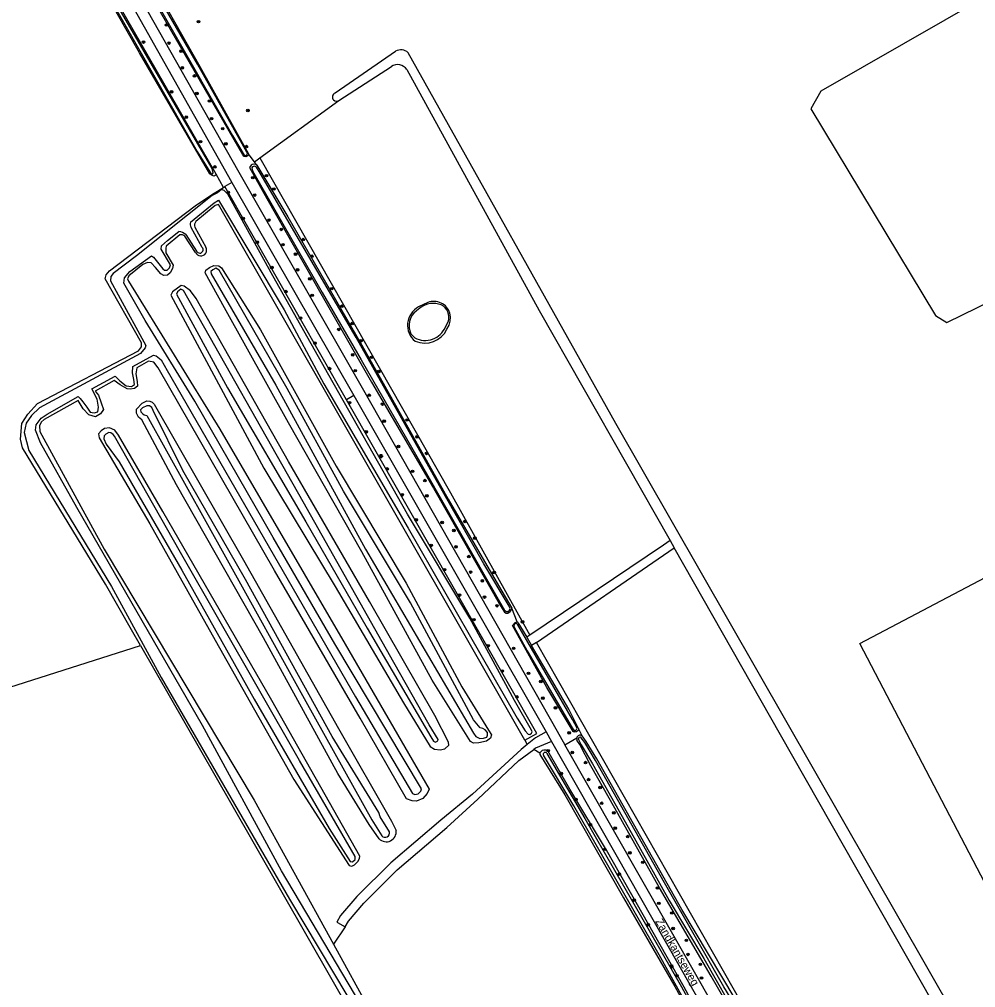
# Model space of a CAD drawing. Extents: x 140000 to 143000, y 403500 to 406000.
# Drawn here: x 140149.8 to 140448.3, y 404654.9 to 404957.2 of the extents above; entities that cross this region are included whole.
import ezdxf

# ---------------------------------------------------------------- set-up
doc = ezdxf.new("R2010")
doc.units = 0
for name, color, linetype in [('gg-anno-openbare ruimte label', 7, 'Continuous'), ('gg-knt-bronhoudergrens', 7, 'Continuous'), ('gg-knt-verharding', 7, 'Continuous'), ('gg-kntw-bovenkant insteek waterloop', 7, 'Continuous'), ('gg-kntw-waterlijn', 7, 'Continuous'), ('gt-grn-groengrens', 7, 'Continuous'), ('gt-grn-vlakafsluiter', 7, 'Continuous'), ('gt-grn-weggrens', 7, 'Continuous'), ('gt-symb-boom', 7, 'Continuous'), ('gt-symb-lichtmast', 7, 'Continuous')]:
    doc.layers.add(name, color=color, linetype=linetype)

# ---------------------------------------------------------------- blocks, each defined once
blk = doc.blocks.new('gt0-BOOM')
at = {"layer": 'gt-symb-boom'}
for radius in [0.4, 0.2]:
    blk.add_circle((0, 0), radius, dxfattribs=at)
blk = doc.blocks.new('gt0-LMAST')
at = {"layer": 'gt-symb-lichtmast'}
for p, q in [((-0.18, 0.17), (-0.45, 0.44)), ((-0.01, 0.25), (-0.01, 0.62)), ((0.17, 0.17), (0.44, 0.44)), ((-0.26, 0), (-0.63, 0)), ((-0.18, -0.18), (-0.45, -0.45)), ((-0.01, -0.25), (-0.01, -0.63)), ((0.44, -0.45), (0.17, -0.18)), ((0.24, 0), (0.62, 0))]:
    blk.add_line(p, q, dxfattribs=at)
blk.add_circle((-0.01, 0), 0.25, dxfattribs=at)

msp = doc.modelspace()

# ---------------------------------------------------------------- linework, layer by layer
at = {"layer": 'gg-knt-bronhoudergrens'}
for p, q in [((140224.82, 404913.91), (140249.53, 404931.86)), ((140311.14, 404762.64), (140354.13, 404792.19)), ((140395.71, 404614.2), (140311.14, 404762.64))]:
    msp.add_line(p, q, dxfattribs=at)
for points in [[(140224.82, 404913.91), (140284.32, 404809.37), (140309.13, 404764.88)], [(140352.87, 404794.42), (140350.82, 404793.03), (140309.13, 404764.88)]]:
    msp.add_lwpolyline(points, dxfattribs=at)
at = {"layer": 'gg-knt-verharding'}
for p, q in [((140216.06, 404906.21), (140254.21, 404839.77)), ((140254.21, 404839.77), (140314.17, 404734.67)), ((140314.17, 404734.67), (140315.85, 404731.72))]:
    msp.add_line(p, q, dxfattribs=at)
for points in [[(140015.47, 405269.29), (140093.98, 405129.51), (140149.27, 405031.32), (140217.82, 404910.2), (140257.23, 404841.36), (140317.65, 404734.89), (140320.04, 404730.7)], [(140012.59, 405267.65), (140091.15, 405127.98), (140215.94, 404906.42), (140216.06, 404906.21)], [(140315.85, 404731.72), (140371.43, 404634.06), (140428.2, 404534.96)], [(140385.43, 404616.2), (140375.32, 404633.79), (140320.04, 404730.7)]]:
    msp.add_lwpolyline(points, dxfattribs=at)
at = {"layer": 'gg-kntw-bovenkant insteek waterloop'}
for p, q in [((140267.19, 404947.17), (140248.32, 404934.15)), ((140249.53, 404931.86), (140265.87, 404942.46)), ((140213.45, 404904.71), (140213.86, 404904.97)), ((140251.83, 404838.42), (140213.86, 404904.97)), ((140204.49, 404892.26), (140208, 404886)), ((140204.73, 404884.34), (140201.41, 404889.42)), ((140277.28, 404868.8), (140274.38, 404867.36)), ((140352.87, 404794.42), (140354.13, 404792.19)), ((140308.15, 404764.22), (140309.66, 404761.63)), ((140325.38, 404733.48), (140325.47, 404733.44))]:
    msp.add_line(p, q, dxfattribs=at)
for points in [[(140211.16, 404908.87), (140180.94, 404961.44), (140141.23, 405031.76), (140139.9, 405034.84), (140106.05, 405095.67), (140094.79, 405114.98), (140091.84, 405120.15), (140090.08, 405122.65), (140083.85, 405133.69), (140065.63, 405166.05), (140041.91, 405207.98), (140024.47, 405240.13), (140013.65, 405260.82), (140011.23, 405265.23), (140010.6, 405265.67), (140009.82, 405265.58), (140008.99, 405264.87), (140008.83, 405264.18), (140008.78, 405263.08)], [(140221.32, 404915.12), (140221.27, 404914.79), (140221.05, 404914.55), (140220.48, 404914.22), (140219.96, 404914.32), (140219.52, 404914.81), (140187.96, 404969.55), (140169.57, 405002.2), (140142.8, 405050.33), (140118.75, 405092.41), (140116.73, 405096.57), (140115.86, 405097.86), (140114.98, 405099.37), (140049.1, 405216.97), (140022.7, 405263.69), (140021.65, 405265.62), (140020.77, 405267.14)], [(140022.22, 405268.24), (140023.21, 405266.5), (140053.29, 405214.48), (140091.86, 405144.38), (140113.34, 405106.43), (140117.71, 405098.64), (140120.4, 405093.58), (140120.66, 405093.21), (140144.47, 405051.89), (140170.87, 405004.52), (140206.08, 404942.46), (140221.32, 404915.12)], [(140211.16, 404908.87), (140211.14, 404908.72), (140210.91, 404908.37), (140210.58, 404908.25), (140209.72, 404908.53), (140209.26, 404908.96), (140187.27, 404946.74), (140161.57, 404991.94), (140139.8, 405030.55), (140137.59, 405034.4), (140115.65, 405072.87), (140094.35, 405111.42), (140090.14, 405119.58), (140088.48, 405122.42), (140067.9, 405158.36), (140046.49, 405195.64), (140033.29, 405218.1), (140022.54, 405238.57), (140008.78, 405263.08)], [(140442.04, 404645.58), (140335.94, 404830.98), (140271.07, 404946.74)], [(140270.7, 404941.52), (140312.04, 404866.27), (140352.87, 404794.42)], [(140223.9, 404911.62), (140223.53, 404911.88), (140222.95, 404911.95), (140222.42, 404911.84), (140222.14, 404911.63), (140221.62, 404910.94), (140226.98, 404901.2), (140244.29, 404870.8), (140259.7, 404843.87), (140278.99, 404810.74), (140299.93, 404774.07), (140301.18, 404772.08), (140301.75, 404771.81), (140302.26, 404771.76), (140302.96, 404772.32), (140303.37, 404772.76), (140303.44, 404773.3)], [(140223.9, 404911.62), (140233.54, 404895.47), (140256.69, 404855.44), (140277.3, 404818.65)], [(140187.6, 404761.63), (140184.79, 404766.54), (140176.64, 404780.8), (140150.73, 404823.38), (140150.08, 404826.13), (140150.53, 404831.02), (140152.4, 404833.86), (140155.43, 404837.23), (140186.91, 404853.66), (140187.91, 404854.92), (140187.84, 404856.18), (140176.52, 404876.1), (140176.81, 404877.43), (140177.94, 404878.64), (140204.66, 404898.91), (140210.03, 404902.56), (140213.45, 404904.71)], [(140307.53, 404732.16), (140211.89, 404899.32), (140210.91, 404899.04), (140204.82, 404894)], [(140199.83, 404889.88), (140195.55, 404886.34), (140195.47, 404885.75), (140195.43, 404884.24), (140197.78, 404880.37), (140197.6, 404879.41), (140196.85, 404878.03), (140195.98, 404877.29), (140194.85, 404877.16), (140193.93, 404877.71), (140192.2, 404879.69), (140190.89, 404881.09), (140189.77, 404881.24), (140188.29, 404880.66), (140183.94, 404877.09), (140183.51, 404876.12), (140183.78, 404875.39), (140212.37, 404829.24), (140251.41, 404762.13), (140277.65, 404716.79), (140277.08, 404715.48), (140275.75, 404713.92), (140273.68, 404713.11), (140272.36, 404713.16), (140270.61, 404713.84), (140256.18, 404739.03), (140229.39, 404785.06), (140193.13, 404848.39), (140191.71, 404850.12), (140190.07, 404850.41), (140186.41, 404848.31), (140186.16, 404846.52), (140186.49, 404844.12), (140186.61, 404842.59), (140185.71, 404841.88), (140184.33, 404841.74), (140183.4, 404841.77), (140181.23, 404843.08), (140179.37, 404844.4), (140173.38, 404841.05), (140174.41, 404839.79), (140175.29, 404837.48), (140175.98, 404835.35), (140175.1, 404834.03), (140173.56, 404833.08), (140171.48, 404833.72), (140169.63, 404835.56), (140168.09, 404838.13), (140157.48, 404832.27), (140156.59, 404831.44), (140156.04, 404830.22), (140156.13, 404828.53), (140176.26, 404791.76), (140223.05, 404713.36), (140247.77, 404668.46)], [(140233.77, 404831.23), (140213.74, 404867.14), (140207.72, 404878.05), (140207.94, 404878.8), (140209.11, 404879.73), (140210.45, 404880.33), (140212.05, 404880.2), (140212.88, 404879.61), (140225.01, 404860.25), (140248.69, 404817.66), (140270.5, 404781.1), (140287.89, 404748.74), (140296.15, 404735.25), (140297.18, 404733.81), (140296.82, 404732.72), (140295.53, 404731.84), (140293.21, 404731.27), (140291.54, 404731.21), (140290.6, 404731.73), (140278.63, 404750.88), (140256.64, 404790.88), (140233.77, 404831.23)], [(140233.73, 404819.12), (140204.92, 404870.01), (140203.14, 404872.44), (140201.21, 404873.82), (140200.22, 404874.03), (140197.55, 404872.12), (140197, 404871.03), (140226.04, 404817.06), (140248.29, 404780.09), (140269.64, 404743.79), (140278.02, 404730.13), (140279.38, 404729.34), (140281.11, 404729.09), (140282.55, 404729.36), (140283.83, 404730.6), (140283.74, 404731.53), (140279.42, 404739.85), (140259.02, 404775.38), (140233.73, 404819.12)], [(140283.23, 404860.42), (140283.87, 404861.67), (140284.23, 404862.93), (140284.35, 404864.2), (140284.17, 404865.49)], [(140262.04, 404701.34), (140258.96, 404705.82), (140249.2, 404721.72), (140225.98, 404764.05), (140198.79, 404811.82), (140187.95, 404832.12), (140186.97, 404832.98), (140186.31, 404834.25), (140186.33, 404835.48), (140188.08, 404837.36), (140189.54, 404838.03), (140190.49, 404837.97), (140191.24, 404837.62), (140191.85, 404837), (140219.72, 404788.3), (140249.36, 404735.74), (140265.88, 404706.86), (140267.34, 404703.93)], [(140307.53, 404732.16), (140311.27, 404734.24), (140251.83, 404838.42)], [(140177.9, 404829.59), (140176.37, 404829.47), (140175.32, 404828.73), (140174.42, 404827.77), (140174.65, 404826.48), (140190.52, 404799.7), (140210.88, 404763.31), (140235.4, 404719.82), (140252.72, 404692.94), (140253.58, 404692.78), (140254.4, 404693.21), (140255.41, 404694.23), (140255.93, 404695.18), (140256.03, 404695.92), (140228.57, 404744.54), (140194.55, 404803.51), (140180.69, 404827.34), (140179.56, 404828.87), (140177.9, 404829.59)], [(140277.3, 404818.65), (140283.61, 404807.37), (140299.29, 404780.36), (140303.44, 404773.3)], [(140438.67, 404643.61), (140387.31, 404733.8), (140354.13, 404792.19)], [(140324.32, 404735.73), (140324.23, 404735.17), (140323.67, 404734.71), (140322.98, 404734.62), (140322.66, 404734.78), (140314.4, 404748.53), (140303.67, 404767.91), (140304.55, 404768.81), (140305.1, 404769.03)], [(140305.1, 404769.03), (140305.49, 404768.66), (140305.92, 404768.05), (140308.15, 404764.22)], [(140187.6, 404761.63), (140215.62, 404712.61), (140255.48, 404643.05), (140287.3, 404589.57), (140300.13, 404568.51), (140301.49, 404567.23), (140301.93, 404567.32)], [(140324.32, 404735.73), (140321.24, 404741.81), (140309.66, 404761.63)], [(140392.12, 404617.25), (140388.44, 404625.36), (140386.36, 404629.4), (140377.34, 404644.38), (140356.59, 404679.29), (140330.03, 404726.24), (140326.73, 404731.7), (140325.47, 404733.44)], [(140388.6, 404618.02), (140379.67, 404634.16), (140365.68, 404658.45), (140349.61, 404686.04), (140335.6, 404710.85), (140328.16, 404724.15), (140324.67, 404730.75), (140323.82, 404732.13)], [(140312.21, 404728.05), (140312.18, 404727.65), (140319.98, 404715.03), (140338.35, 404682.93), (140354.32, 404655.19), (140368.02, 404630.46), (140380.88, 404608.33)], [(140425.86, 404533.65), (140408.47, 404564.52), (140394.24, 404589.46), (140381.38, 404612.25), (140368.52, 404634.28), (140357.25, 404655.04), (140333, 404697.74), (140321.59, 404716.82), (140314.67, 404728.77), (140314.26, 404729.04), (140313.49, 404728.99), (140312.97, 404728.86), (140312.44, 404728.41), (140312.22, 404728.17), (140312.21, 404728.05)], [(140247.77, 404668.46), (140259.37, 404647.38), (140302.77, 404572.58), (140303.79, 404570.47), (140304.12, 404569.33), (140303.38, 404568.24), (140302.52, 404567.44), (140301.93, 404567.32)]]:
    msp.add_lwpolyline(points, dxfattribs=at)
for centre, radius, start, end in [((140268.85, 404944.42), 3.22, 46.158, 120.9997), ((140267.8, 404939.5), 3.53, 34.7412, 123.1813), ((140248.77, 404932.92), 1.31, 110.3403, 224.5398), ((140248.77, 404932.92), 1.3, 224.4593, 305.6042), ((140206.43, 404892.8), 2.01, 143.3638, 195.4168), ((140200.19, 404888.14), 1.77, 46.2961, 101.6984), ((140206.38, 404885.14), 1.84, 205.9472, 28.1185), ((140277.3, 404861.68), 6.38, 117.2165, 231.4357), ((140279.1, 404863.76), 5.35, 18.7766, 109.91), ((140276.34, 404863.7), 7.63, 246.6925, 334.5032), ((140324.78, 404732.59), 1.07, 56.0891, 168.1615), ((140324.79, 404732.59), 1.07, 168.238, 205.514), ((140264.28, 404703.47), 3.09, 223.5978, 8.5251)]:
    msp.add_arc(centre, radius, start, end, dxfattribs=at)
at = {"layer": 'gg-kntw-waterlijn'}
for p, q in [((140206.85, 404885.93), (140203.34, 404892.18)), ((140201.73, 404889.97), (140205.09, 404884.83)), ((140274.8, 404867), (140273.69, 404866.13)), ((140282.77, 404861.12), (140283.68, 404862.92)), ((140271.96, 404858.95), (140273.2, 404857.69))]:
    msp.add_line(p, q, dxfattribs=at)
for points in [[(140176.54, 404990.61), (140216.26, 404920.9), (140219.92, 404914.75), (140220.45, 404914.61), (140220.87, 404914.99), (140220.95, 404915.4), (140220.75, 404915.7), (140205.32, 404943.14), (140182.22, 404983.23)], [(140169.09, 404979.57), (140205.29, 404915.94), (140209.38, 404909.19), (140209.68, 404908.91), (140210.02, 404908.9), (140210.23, 404909.22), (140209.96, 404910.55), (140177.2, 404967.09)], [(140254.88, 404857.88), (140224.95, 404909.16), (140223.81, 404911), (140223.18, 404911.35), (140222.48, 404911.11), (140222.27, 404910.82), (140222.55, 404909.85), (140244.23, 404871.87), (140256.45, 404850.88), (140272.21, 404823.6), (140295.53, 404782.53), (140301.23, 404772.75), (140301.77, 404772.3), (140302.2, 404772.32), (140302.74, 404772.71), (140302.94, 404773.24), (140302.64, 404774), (140294.76, 404787.19), (140282.75, 404808.22), (140254.88, 404857.88)], [(140203.16, 404893.84), (140210.6, 404899.86), (140211.93, 404900.7), (140232.4, 404866.47), (140244.78, 404843.36), (140271.17, 404798.3), (140305.17, 404739), (140307.65, 404735.02), (140308.58, 404733.97), (140309.13, 404733.93), (140309.64, 404734.35), (140309.81, 404734.72), (140309.61, 404735.21), (140304.3, 404744.51), (140290.41, 404770.16), (140270.87, 404802.64), (140246.38, 404846.04), (140228.83, 404877.07), (140214.85, 404902.62), (140213.64, 404903.75), (140212.83, 404904.03), (140211.6, 404903.03), (140209.97, 404902.18), (140186.31, 404883.34), (140179.01, 404877.82), (140178.28, 404876.84), (140178.2, 404875.48), (140180.57, 404871.12), (140189.28, 404855.37), (140189.06, 404854.56), (140187.61, 404852.88), (140156.03, 404835.89), (140153.49, 404833.43), (140151.88, 404831.06), (140151.27, 404828.12), (140152.67, 404822.53), (140178.47, 404780.1), (140193.97, 404751.64), (140234.13, 404682.47), (140256.75, 404644.46)], [(140258.32, 404646.21), (140231.61, 404691.32), (140206.93, 404736.68), (140167.67, 404804.77), (140156.38, 404824.9), (140154.79, 404828.95), (140154.95, 404830.59), (140156.51, 404832.64), (140158.44, 404833.94), (140168.08, 404839.36), (140168.74, 404838.79), (140169.58, 404837.71), (140170.81, 404836.03), (140171.88, 404834.5), (140173.15, 404834.26), (140174.22, 404834.64), (140174.45, 404836.03), (140174.08, 404838.58), (140172.4, 404841.76), (140179.63, 404845.79), (140181.13, 404844.25), (140183.09, 404842.77), (140184.76, 404842.58), (140185.73, 404843.11), (140185.52, 404844.68), (140185.04, 404846.85), (140185.16, 404848.82), (140191.6, 404852.31), (140192.5, 404852.12), (140194.05, 404850.85), (140195.87, 404847.49), (140254.65, 404745.63), (140272.46, 404715.44), (140273.18, 404715.12), (140274.22, 404715.35), (140275.08, 404716.21), (140275.24, 404716.95), (140248.2, 404762.14), (140228.94, 404795.37), (140204.54, 404837.97), (140189.04, 404863.16), (140182.41, 404874.82), (140182.54, 404876.49), (140184.26, 404878.46), (140190.96, 404883.34), (140191.65, 404882.93), (140194.55, 404879.28), (140195.09, 404878.83), (140195.86, 404878.83), (140196.64, 404879.53), (140196.98, 404880.47), (140194, 404885.39), (140194.15, 404886.5), (140196.04, 404888.08), (140199.52, 404890.9)], [(140250.91, 404809.81), (140233.32, 404841.89), (140212.17, 404878.84), (140211.07, 404879.45), (140210.16, 404878.99), (140209.57, 404878.47), (140209.65, 404877.68), (140229.83, 404842.94), (140257.79, 404791.78), (140291.51, 404734.28), (140292.22, 404733.26), (140293.54, 404732.68), (140294.61, 404732.69), (140295.65, 404733.04), (140295.93, 404733.72), (140295.84, 404734.52), (140295.14, 404735.36), (140294.48, 404735.8), (140293.55, 404735.95), (140291.51, 404738.51), (140271.86, 404774.95), (140250.91, 404809.81)], [(140238.39, 404806.49), (140201.04, 404872.55), (140200.17, 404872.95), (140199.09, 404872.11), (140198.8, 404871.36), (140214.7, 404842.12), (140239.22, 404800.23), (140258.29, 404767.12), (140278.17, 404733.15), (140279.08, 404731.77), (140279.7, 404731.48), (140280.34, 404731.9), (140280.45, 404732.34), (140277.7, 404736.86), (140266.61, 404756.38), (140238.39, 404806.49)], [(140265.28, 404703.51), (140262.42, 404708.19), (140261.94, 404709.53), (140247.38, 404733.3), (140220.36, 404782.28), (140200.79, 404816.27), (140191.49, 404835.02), (140191.06, 404835.96), (140190.39, 404836.46), (140189.5, 404836.46), (140188.16, 404835.92), (140187.54, 404835.25), (140187.62, 404834.64), (140188.16, 404834.07), (140188.73, 404833.72), (140189.51, 404833.47), (140214.14, 404789.34), (140239.15, 404744.2), (140259.83, 404707.27), (140262.87, 404702.27)], [(140178.33, 404828.06), (140177.71, 404828.22), (140176.77, 404827.67), (140176.24, 404827.09), (140176.14, 404826.17), (140176.82, 404824.53), (140180.92, 404819.03), (140200.51, 404785.2), (140223.1, 404744.88), (140246.43, 404704.52), (140252.98, 404694.24), (140253.78, 404694.15), (140254.59, 404694.88), (140254.56, 404695.81), (140237.16, 404725.8), (140200.08, 404790.67), (140179.47, 404827.05), (140179.05, 404827.5), (140178.33, 404828.06)], [(140304.92, 404768.53), (140304.49, 404768.39), (140304.25, 404768.2), (140304.15, 404767.64), (140308.3, 404760.02), (140322.31, 404735.92), (140322.99, 404735.17), (140323.36, 404735.12), (140323.66, 404735.44), (140323.83, 404735.82), (140322.41, 404738.57), (140305.4, 404768.15), (140304.92, 404768.53)], [(140324.31, 404732.37), (140325.15, 404730.66), (140328.69, 404724.75), (140341.68, 404701.67), (140352.64, 404682.05), (140363.42, 404663.94), (140374.6, 404644.35), (140389.5, 404617.8), (140390.16, 404616.99), (140390.56, 404616.62), (140390.72, 404616.6), (140391.09, 404616.87), (140391.05, 404617.15), (140389.06, 404621.22), (140387.78, 404624.07), (140379.64, 404638.74), (140369.68, 404655.15), (140351.15, 404687.56), (140329.63, 404725.8), (140326.29, 404731.37), (140325.14, 404732.86)], [(140366.34, 404634.64), (140349.45, 404665.12), (140322.79, 404711.62), (140313.33, 404727.38)], [(140314.46, 404727.94), (140326.3, 404707.61), (140356.46, 404655.11), (140369.33, 404631.57), (140382.68, 404608.72), (140424.78, 404534.26), (140443.74, 404500.91), (140447.27, 404494.14)]]:
    msp.add_lwpolyline(points, dxfattribs=at)
for centre, radius, start, end in [((140205.41, 404893.25), 2.33, 165.3987, 207.2436), ((140199.3, 404887.27), 3.63, 47.9326, 86.4673), ((140206.07, 404885.22), 1.05, 201.7654, 42.216), ((140278.97, 404861.85), 6.62, 67.8129, 129.031), ((140279.61, 404864.16), 4.25, 343.0902, 64.0641), ((140277.16, 404861.5), 5.79, 126.8709, 206.0767), ((140276.39, 404863.86), 6.94, 242.6853, 336.7559), ((140324.75, 404732.57), 0.483, 36.5221, 204.8325), ((140313.9, 404727.65), 0.634, 27.8996, 204.8664), ((140263.93, 404703.18), 1.39, 220.7547, 13.7936)]:
    msp.add_arc(centre, radius, start, end, dxfattribs=at)
at = {"layer": 'gt-grn-groengrens'}
for p, q in [((140223.12, 404912.68), (140224.82, 404913.91)), ((140213.45, 404904.71), (140211.16, 404908.87)), ((140305.1, 404769.03), (140303.44, 404773.3)), ((140309.13, 404764.88), (140308.15, 404764.22)), ((140311.14, 404762.64), (140309.66, 404761.63)), ((140325.47, 404733.44), (140324.32, 404735.73)), ((140307.53, 404732.16), (140308.26, 404730.76)), ((140312.21, 404728.05), (140310.36, 404729.25)), ((140251.48, 404673.83), (140247.77, 404668.46))]:
    msp.add_line(p, q, dxfattribs=at)
for points in [[(140451.59, 404964.43), (140399.93, 404934.76), (140396.8, 404929.18), (140435.78, 404864.65), (140439.27, 404862.52), (140496.9, 404890.71)], [(140466.21, 404658.85), (140464.51, 404661.82), (140412.12, 404762.34), (140455.21, 404785.01), (140466.95, 404790.83)], [(140095.21, 404744.25), (140100.98, 404734.11), (140187.6, 404761.63)], [(140308.26, 404730.76), (140306.38, 404729.25), (140291.24, 404715.28), (140281.28, 404707.14), (140265.66, 404693.82), (140255.11, 404683.28), (140250.01, 404677.34), (140248.86, 404675.3), (140249.07, 404675.18), (140251.48, 404673.83)], [(140251.48, 404673.83), (140252.48, 404675.61), (140257.31, 404681.24), (140267.69, 404691.62), (140283.23, 404704.86), (140292.83, 404713.71), (140305.72, 404725.73), (140310.36, 404729.25)]]:
    msp.add_lwpolyline(points, dxfattribs=at)
at = {"layer": 'gt-grn-vlakafsluiter'}
for p, q in [((140222.46, 404913.57), (140221.32, 404915.12)), ((140223.12, 404912.68), (140222.46, 404913.57)), ((140223.9, 404911.62), (140223.12, 404912.68))]:
    msp.add_line(p, q, dxfattribs=at)
at = {"layer": 'gt-grn-weggrens'}
for p, q in [((140216.06, 404906.21), (140213.86, 404904.97)), ((140254.21, 404839.77), (140251.83, 404838.42)), ((140320.04, 404730.7), (140323.74, 404732.81))]:
    msp.add_line(p, q, dxfattribs=at)
for points in [[(140314.17, 404734.67), (140310.9, 404732.87), (140308.26, 404730.76)], [(140315.85, 404731.72), (140310.88, 404729.64), (140310.36, 404729.25)]]:
    msp.add_lwpolyline(points, dxfattribs=at)

# ---------------------------------------------------------------- block references
at = {"layer": 'gt-symb-boom'}
for p in [(140195.66, 404955.39), (140205.66, 404956.43), (140188.49, 404950.07), (140196.47, 404949.75), (140200.28, 404947.23), (140200.64, 404942.02), (140204.43, 404939.5), (140197.27, 404934.52), (140205.16, 404933.99), (140209.09, 404931.68), (140201.87, 404926.6), (140221.1, 404928.72), (140209.76, 404926.14), (140213.23, 404923.04), (140206.3, 404918.97), (140214.19, 404918.3), (140220.63, 404917.43), (140210.76, 404911.08), (140226.92, 404908.37), (140222.65, 404907.74), (140215, 404903.16), (140223.21, 404902.29), (140229.17, 404904.18), (140219.65, 404895.02), (140227.67, 404894.49), (140231.52, 404891.58), (140224.02, 404887.58), (140238.37, 404888.4), (140232.04, 404886.8), (140235.98, 404883.84), (140241.11, 404883.19), (140228.55, 404879.7), (140236.6, 404878.96), (140240.43, 404876.14), (140232.96, 404872.16), (140247.26, 404873.07), (140241.15, 404871.01), (140250.4, 404867.58), (140237.5, 404863.9), (140249.45, 404860.36), (140253.69, 404862.22), (140242.04, 404856.04), (140256.44, 404856.82), (140253.8, 404852.44), (140259.7, 404851.63), (140246.6, 404848.12), (140254.62, 404847.47), (140261.94, 404847.23), (140258.97, 404839.8), (140252.83, 404837.46), (140263.11, 404837.05), (140263.64, 404831.7), (140270.76, 404832.06), (140258.03, 404828.4), (140273.93, 404826.83), (140268.08, 404823.8), (140276.88, 404821.64), (140264.61, 404816.8), (140272.47, 404816.06), (140276.36, 404813.16), (140269.31, 404808.74), (140276.96, 404808.38), (140273.61, 404800.9), (140281.71, 404800.09), (140288.87, 404800.37), (140285.41, 404797.56), (140291.92, 404795.18), (140278.3, 404792.92), (140286.07, 404792.47), (140290.05, 404789.43), (140282.46, 404785.33), (140290.62, 404784.6), (140297.99, 404784.48), (140294.29, 404781.85), (140287.18, 404777.41), (140294.96, 404776.79), (140298.86, 404774.08), (140291.6, 404769.74), (140306.8, 404769.07), (140296.12, 404761.6), (140304.05, 404760.77), (140300.53, 404753.7), (140308.7, 404752.97), (140312.53, 404750.42), (140305.1, 404745.62), (140313.15, 404745.24), (140317.12, 404742.23), (140321.39, 404734.4), (140314.86, 404728.85), (140322.36, 404728.28), (140326.51, 404725.11), (140318.91, 404721.73), (140327.44, 404719.81), (140331.04, 404717.34), (140323.46, 404713.59), (140331.54, 404712.41), (140335.34, 404709.43), (140328.01, 404705.67), (140335.77, 404704.66), (140339.65, 404702.01), (140332.48, 404698.05), (140340.3, 404696.96), (140344.35, 404693.97), (140337.04, 404690.26), (140348.96, 404685.95), (140341.69, 404682.18), (140349.35, 404681.17), (140353.41, 404678.16), (140346.02, 404674.48), (140353.82, 404673.31), (140357.96, 404669.63), (140358.46, 404665.23), (140362.33, 404662.12), (140355.01, 404658.56), (140362.68, 404657.87)]:
    msp.add_blockref('gt0-BOOM', p, dxfattribs=at)
at = {"layer": 'gt-symb-lichtmast'}
for p in [(140262.68, 404820.81), (140353.37, 404661.49)]:
    msp.add_blockref('gt0-LMAST', p, dxfattribs=at)

# ---------------------------------------------------------------- texts
at = {"layer": 'gg-anno-openbare ruimte label'}
msp.add_text('Zandkantseweg', height=2.5, rotation=300, dxfattribs=at).set_placement((140348.17, 404675.56))

doc.saveas('drawing.dxf')
